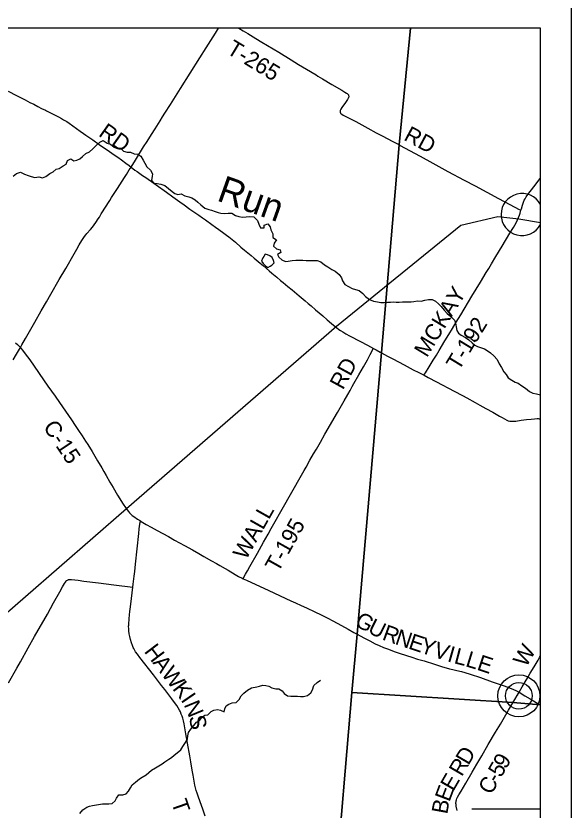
# Model space of a CAD drawing. Extents: x 0 to 34, y 0 to 22.
# Drawn here: x 7.205 to 9.17, y 17.655 to 20.469 of the extents above; entities that cross this region are included whole.
import ezdxf

# ---------------------------------------------------------------- set-up
doc = ezdxf.new("R2010")
doc.units = 0
for name, color, linetype in [('Default', 7, 'Continuous'), ('GM_X_County_Road', 7, 'Continuous'), ('GM_X_County_Road_Text', 7, 'Continuous'), ('GM_X_Interstate_Shield', 7, 'Continuous'), ('GM_X_Minor_Lake', 7, 'Continuous'), ('GM_X_Minor_River', 7, 'Continuous'), ('GM_X_Minor_River_Text', 7, 'Continuous'), ('GM_X_Rail_Line', 7, 'Continuous'), ('GM_X_State_Shield', 7, 'Continuous'), ('GM_X_Township_Road', 7, 'Continuous'), ('GM_X_Township_Road_Text', 7, 'Continuous'), ('GM_X_Unincorporated', 7, 'Continuous'), ('GM_X_Unincorporated_Location', 7, 'Continuous'), ('SH_Cut_Line', 7, 'Continuous'), ('SH_Data', 7, 'Continuous')]:
    doc.layers.add(name, color=color, linetype=linetype)

msp = doc.modelspace()

# ---------------------------------------------------------------- linework, layer by layer
at = {"layer": 'Default'}
msp.add_lwpolyline([(8.3334, 17.361), (8.3935, 18.0719), (8.4126, 18.2788), (8.4989, 19.2757), (8.562, 20.012), (8.6014, 20.4252), (3.5682, 20.4252), (3.5424, 20.1754), (3.5231, 19.8516), (3.5169, 19.7823), (3.5125, 19.7343), (3.5092, 19.6961), (3.5066, 19.6647), (3.4966, 19.5464), (3.4903, 19.4759), (3.4748, 19.2963), (3.47, 19.2407), (3.2768, 17.1355)], dxfattribs=at)
for points in [[(9.0621, 18.0279), (9.0621, 20.4252), (8.6014, 20.4252), (8.562, 20.012), (8.4989, 19.2757), (8.4126, 18.2788), (8.3935, 18.0719), (8.9638, 18.036), (9.0619, 18.0279)], [(8.4279, 13.6252), (9.0621, 13.6252), (9.0621, 18.0279), (9.0619, 18.0279), (8.9638, 18.036), (8.3935, 18.0719), (8.3334, 17.361), (8.3307, 17.3314), (8.3286, 17.3076), (8.2895, 16.85), (8.2031, 16.209), (8.146, 15.4642), (8.137, 15.3372), (8.1234, 15.1688), (8.3761, 15.1587), (8.4023, 15.1576), (8.4024, 15.1386)]]:
    msp.add_lwpolyline(points, close=True, dxfattribs=at)
at = {"layer": 'GM_X_County_Road'}
msp.add_line((8.964, 18.0355), (8.9861, 18.0728), dxfattribs=at)
for points in [[(7.6123, 19.933), (7.6276, 19.9574), (7.6569, 20.0042), (7.6695, 20.0242), (7.6847, 20.0484), (7.6975, 20.0689), (7.7151, 20.0967), (7.724, 20.1109), (7.7322, 20.124), (7.7514, 20.1546), (7.7874, 20.2112), (7.8562, 20.3199), (7.8784, 20.3551), (7.8953, 20.3819), (7.9114, 20.4077), (7.9221, 20.4252)], [(7.2208, 19.2936), (7.2261, 19.3034), (7.2389, 19.3261), (7.253, 19.351), (7.2716, 19.3833), (7.2945, 19.4238), (7.3129, 19.4563), (7.3284, 19.4832), (7.358, 19.5343), (7.381, 19.5741), (7.4104, 19.6252), (7.4198, 19.642), (7.4287, 19.6577), (7.4376, 19.6727), (7.4427, 19.6806), (7.4474, 19.6872), (7.4517, 19.6925), (7.4557, 19.6973), (7.4685, 19.7117), (7.476, 19.7207), (7.482, 19.7286), (7.488, 19.7372), (7.4958, 19.7492), (7.5, 19.7561), (7.5069, 19.7672), (7.5244, 19.795), (7.532, 19.8071), (7.537, 19.815), (7.5436, 19.8255), (7.5522, 19.8392), (7.5638, 19.8575), (7.5723, 19.8706), (7.5892, 19.8966), (7.5956, 19.9065), (7.6059, 19.9228), (7.6123, 19.933)], [(7.2034, 19.3104), (7.2104, 19.3042), (7.2162, 19.2985), (7.2208, 19.2936)], [(7.195, 19.2497), (7.2071, 19.2707), (7.2136, 19.282), (7.2175, 19.2883), (7.2198, 19.292), (7.2208, 19.2936)], [(7.2208, 19.2936), (7.2222, 19.2921), (7.2281, 19.2848), (7.2379, 19.272), (7.2539, 19.2498), (7.3179, 19.1573), (7.3431, 19.1218), (7.3587, 19.0994), (7.3697, 19.0836), (7.3913, 19.0525), (7.4015, 19.0376), (7.415, 19.0175), (7.4264, 19.0004), (7.4392, 18.9813), (7.4515, 18.9627), (7.4595, 18.95), (7.4747, 18.9251), (7.494, 18.8925), (7.5086, 18.8672), (7.5157, 18.8548), (7.5241, 18.8402), (7.5374, 18.8164), (7.5484, 18.7976), (7.5644, 18.771), (7.5843, 18.7395), (7.5928, 18.7266), (7.5982, 18.719), (7.6032, 18.7127), (7.6073, 18.7081), (7.6116, 18.7037), (7.6167, 18.6993), (7.6226, 18.6948), (7.6348, 18.6864), (7.6452, 18.6798)], [(7.6452, 18.6798), (7.6479, 18.6781), (7.666, 18.6671), (7.6833, 18.6573), (7.7044, 18.6456), (7.7444, 18.624), (7.7667, 18.6118), (7.8011, 18.593), (7.8294, 18.5774), (7.8528, 18.5645), (7.8705, 18.5542), (7.8975, 18.5388), (7.9147, 18.5288), (7.9271, 18.5217), (7.946, 18.5111), (7.9558, 18.5056), (7.9814, 18.4902), (7.9931, 18.4833), (8.0057, 18.4767), (8.0093, 18.4749)], [(8.0093, 18.4749), (8.0208, 18.4693), (8.0998, 18.4331), (8.1777, 18.3971), (8.194, 18.3895), (8.2148, 18.3797), (8.2335, 18.3713), (8.2629, 18.3579), (8.2859, 18.3468), (8.3086, 18.3352), (8.3266, 18.3255), (8.3572, 18.3088), (8.381, 18.2957)], [(8.381, 18.2957), (8.4013, 18.2845), (8.4128, 18.2783)], [(8.4128, 18.2783), (8.4368, 18.2653), (8.4572, 18.2548), (8.4772, 18.2447), (8.4906, 18.2383), (8.506, 18.2317), (8.5239, 18.2248), (8.5438, 18.2176), (8.5655, 18.2102), (8.6063, 18.1971), (8.627, 18.1905), (8.6496, 18.1836), (8.687, 18.1718), (8.7148, 18.163), (8.7279, 18.1593), (8.7399, 18.1562), (8.752, 18.1535), (8.7659, 18.1503), (8.7822, 18.146), (8.7947, 18.1423), (8.8125, 18.1368), (8.8497, 18.1244), (8.8915, 18.1102), (8.9331, 18.0958), (8.949, 18.0901), (8.9582, 18.0864), (8.9746, 18.0789), (8.9861, 18.0728)], [(8.9861, 18.0728), (9.0067, 18.0605), (9.0252, 18.0491), (9.0584, 18.0296), (9.0621, 18.0274)], [(8.7667, 17.6541), (8.7637, 17.6688), (8.7629, 17.6748), (8.7626, 17.6788), (8.7626, 17.682), (8.7629, 17.6851), (8.7636, 17.6883), (8.7643, 17.6913), (8.7661, 17.696), (8.7682, 17.7006), (8.7727, 17.7089), (8.7806, 17.7223), (8.7977, 17.7511), (8.8199, 17.7892), (8.8367, 17.8183), (8.8538, 17.8471), (8.877, 17.8876), (8.9033, 17.9319), (8.9201, 17.9602), (8.9488, 18.0097), (8.964, 18.0355)]]:
    msp.add_lwpolyline(points, dxfattribs=at)
at = {"layer": 'GM_X_Interstate_Shield'}
msp.add_line((8.8184, 17.6593), (9.0621, 17.6593), dxfattribs=at)
at = {"layer": 'GM_X_Minor_Lake'}
for points in [[(8.079, 19.6112), (8.0772, 19.6088), (8.074, 19.6001), (8.0802, 19.5912), (8.0888, 19.5827), (8.0971, 19.5776), (8.1051, 19.5816), (8.1105, 19.5861)], [(8.1105, 19.5861), (8.1186, 19.5939), (8.1169, 19.6027), (8.1122, 19.6126), (8.104, 19.6189), (8.096, 19.6221), (8.0877, 19.6241), (8.083, 19.6166), (8.079, 19.6112)]]:
    msp.add_lwpolyline(points, dxfattribs=at)
at = {"layer": 'GM_X_Minor_River'}
for points in [[(7.1953, 19.9005), (7.2073, 19.9106), (7.2214, 19.9145), (7.2345, 19.9081), (7.2485, 19.9029), (7.2587, 19.8993), (7.2715, 19.896), (7.2852, 19.8991), (7.2992, 19.8951), (7.3107, 19.8994), (7.3242, 19.9109), (7.3369, 19.9167), (7.3473, 19.9256), (7.358, 19.9284), (7.3718, 19.9369), (7.3822, 19.9428), (7.387, 19.9567), (7.3989, 19.9626), (7.4098, 19.9551), (7.4201, 19.958), (7.4304, 19.9623), (7.4401, 19.9709), (7.452, 19.9809), (7.4647, 19.9875), (7.4767, 19.9979), (7.4891, 20.0101), (7.5014, 20.0209), (7.5141, 20.0275), (7.5272, 20.0177), (7.5397, 20.0148), (7.5531, 20.0039), (7.5633, 19.9988), (7.5754, 19.9997), (7.5859, 19.99), (7.5987, 19.9859), (7.6108, 19.9857), (7.6233, 19.9801), (7.6361, 19.9787), (7.6474, 19.9713), (7.6555, 19.9574), (7.661, 19.9475), (7.6687, 19.9344), (7.6806, 19.9216), (7.6879, 19.9093), (7.6873, 19.8995), (7.6844, 19.8866), (7.6941, 19.8758), (7.7043, 19.8748), (7.7176, 19.8727), (7.7323, 19.8682), (7.745, 19.8577), (7.7577, 19.8464), (7.7678, 19.839), (7.778, 19.8357), (7.7898, 19.8385), (7.8033, 19.8311), (7.8173, 19.8277), (7.8275, 19.8245), (7.8391, 19.8167), (7.8488, 19.8089), (7.8596, 19.7992), (7.8734, 19.7879), (7.8874, 19.7831), (7.8976, 19.7802), (7.91, 19.7754), (7.9202, 19.7725), (7.93, 19.7704)], [(7.93, 19.7704), (7.9429, 19.7683), (7.9566, 19.7695), (7.9691, 19.7693), (7.9823, 19.7614), (7.9943, 19.7581), (8.0072, 19.756), (8.0201, 19.7572), (8.0331, 19.7581), (8.0475, 19.7563), (8.0597, 19.7439), (8.0648, 19.7305), (8.0706, 19.7183), (8.0835, 19.718), (8.0841, 19.7275), (8.0963, 19.7322), (8.1045, 19.721), (8.1077, 19.7111), (8.1142, 19.6961), (8.1147, 19.6832), (8.1275, 19.675), (8.1185, 19.663), (8.1168, 19.6532), (8.1276, 19.6438), (8.1405, 19.6405), (8.1425, 19.6306), (8.1314, 19.6236), (8.1354, 19.6141), (8.1466, 19.6047), (8.159, 19.5988), (8.1689, 19.6001), (8.1822, 19.6021), (8.1955, 19.603), (8.2088, 19.6039), (8.2206, 19.6032), (8.232, 19.6023), (8.2464, 19.6024), (8.2604, 19.6021), (8.2714, 19.6026), (8.2846, 19.5974), (8.297, 19.5873), (8.309, 19.5798), (8.3228, 19.5708), (8.3352, 19.5649), (8.3494, 19.5525), (8.3579, 19.5405), (8.3611, 19.5298), (8.3696, 19.5171), (8.382, 19.5097), (8.3951, 19.5029), (8.4076, 19.4997), (8.42, 19.4956), (8.4327, 19.4847), (8.442, 19.4743), (8.4566, 19.4637), (8.4706, 19.4585), (8.4846, 19.4556), (8.4963, 19.4535), (8.5088, 19.4536), (8.5198, 19.4545), (8.5309, 19.455), (8.5404, 19.4552), (8.5506, 19.455), (8.5612, 19.4548), (8.5734, 19.4553), (8.5829, 19.4552), (8.595, 19.4553), (8.6045, 19.4559), (8.614, 19.4568), (8.6262, 19.4592), (8.6395, 19.4586), (8.6525, 19.4617), (8.6651, 19.4645), (8.6787, 19.4639), (8.6908, 19.4576), (8.7012, 19.449), (8.7098, 19.4393), (8.7209, 19.4258), (8.732, 19.4146), (8.7451, 19.4041), (8.757, 19.3913), (8.7614, 19.3813), (8.7634, 19.3673), (8.7662, 19.3547), (8.7717, 19.3451), (8.7814, 19.338), (8.7964, 19.3298), (8.8088, 19.3215), (8.8196, 19.3107), (8.8293, 19.3025), (8.8391, 19.2978), (8.8534, 19.2929), (8.8636, 19.2893), (8.8733, 19.2834), (8.8853, 19.2752), (8.8972, 19.2643), (8.9084, 19.2512), (8.9153, 19.2363), (8.9234, 19.2228), (8.9322, 19.2082), (8.94, 19.1982)], [(8.8295, 19.3137), (8.8152, 19.3246), (8.8153, 19.3245)], [(8.94, 19.1982), (8.9481, 19.1866), (8.9601, 19.1777), (8.9729, 19.1713), (8.9827, 19.1677), (8.9961, 19.1587), (9.0092, 19.1497), (9.0227, 19.1384), (9.0347, 19.1325), (9.048, 19.1296), (9.0615, 19.1259), (9.0621, 19.1257)], [(7.8046, 17.8948), (7.8117, 17.9068), (7.8135, 17.9185), (7.8156, 17.9306), (7.8234, 17.9419), (7.8347, 17.9553), (7.8437, 17.9665), (7.8548, 17.9728), (7.8633, 17.9832), (7.8741, 17.991), (7.884, 17.9927), (7.8957, 18.0046), (7.9056, 18.009), (7.9186, 18.0121), (7.9288, 18.0096), (7.9416, 18.0033), (7.9441, 18.0143), (7.9488, 18.0241), (7.9584, 18.0303), (7.9707, 18.0354), (7.984, 18.0359), (7.9948, 18.0467), (8.0019, 18.0598), (8.0116, 18.0695), (8.0247, 18.0803), (8.0386, 18.088), (8.0576, 18.0914), (8.0672, 18.0946), (8.0794, 18.0974), (8.09, 18.0972), (8.1006, 18.0939), (8.1107, 18.088), (8.1255, 18.0851), (8.1353, 18.0853), (8.147, 18.0782), (8.1543, 18.0678), (8.166, 18.06), (8.1785, 18.0586), (8.1887, 18.0584), (8.2016, 18.0585), (8.2126, 18.0575), (8.2232, 18.0577), (8.237, 18.0608), (8.2493, 18.0709), (8.2548, 18.0818), (8.2593, 18.0961), (8.2709, 18.1069), (8.2832, 18.1161)], [(7.431, 17.6436), (7.4419, 17.6563), (7.4553, 17.6652), (7.4653, 17.6695), (7.4763, 17.6712), (7.4973, 17.675), (7.511, 17.6773), (7.5247, 17.6775), (7.5342, 17.6773), (7.5452, 17.6782), (7.5556, 17.6879), (7.5611, 17.6976), (7.5686, 17.7092), (7.583, 17.7089), (7.5948, 17.7125), (7.6038, 17.7222), (7.6109, 17.7346), (7.6168, 17.7447), (7.6283, 17.754), (7.6418, 17.7655), (7.6515, 17.7721), (7.6653, 17.7802), (7.6753, 17.788), (7.685, 17.7962), (7.6992, 17.805), (7.7111, 17.812), (7.7226, 17.8193), (7.7323, 17.826), (7.7457, 17.8352), (7.7554, 17.8415), (7.765, 17.8496), (7.7754, 17.8578), (7.7882, 17.8685), (7.7952, 17.8805), (7.8046, 17.8948)]]:
    msp.add_lwpolyline(points, dxfattribs=at)
at = {"layer": 'GM_X_Rail_Line'}
msp.add_lwpolyline([(9.0621, 19.736), (8.9849, 19.7484), (8.9112, 19.7568), (8.7798, 19.7259), (8.3393, 19.3678), (7.5966, 18.7228), (6.6419, 17.8912), (5.6319, 17.0784)], dxfattribs=at)
at = {"layer": 'GM_X_State_Shield'}
msp.add_line((9.0621, 19.7293), (9.0621, 19.8008), dxfattribs=at)
msp.add_arc((8.9969, 19.765), 0.0744, 28.7249, 331.2751, dxfattribs=at)
at = {"layer": 'GM_X_Township_Road'}
for points in [[(7.9936, 20.4252), (8.0093, 20.4153), (8.0254, 20.4058), (8.0537, 20.3888), (8.0754, 20.3756), (8.135, 20.3398), (8.1791, 20.3126), (8.2057, 20.2969), (8.2338, 20.2798), (8.2673, 20.2595), (8.2742, 20.2553), (8.2901, 20.2456), (8.3235, 20.2254), (8.3586, 20.205), (8.3693, 20.1987), (8.3753, 20.1949), (8.3771, 20.1936), (8.3801, 20.1914), (8.3811, 20.1904), (8.3818, 20.1892), (8.3825, 20.1876), (8.3828, 20.1861), (8.3832, 20.1844), (8.3832, 20.1829), (8.3832, 20.1813), (8.3827, 20.1797), (8.3812, 20.1766), (8.3786, 20.1722), (8.3715, 20.1619), (8.359, 20.1441), (8.3555, 20.1384), (8.3542, 20.1362), (8.3531, 20.1338), (8.3526, 20.1324), (8.3523, 20.1308), (8.3522, 20.129), (8.3525, 20.1272), (8.3529, 20.126), (8.3534, 20.1249), (8.3543, 20.1236), (8.3554, 20.1226), (8.3583, 20.1205), (8.3636, 20.1175), (8.3828, 20.1079), (8.408, 20.0945), (8.4509, 20.0706), (8.4805, 20.0547), (8.5019, 20.0434), (8.5392, 20.0236), (8.5623, 20.0114), (8.5631, 20.011)], [(7.1768, 20.202), (7.2066, 20.1866), (7.237, 20.1709), (7.2541, 20.1622), (7.2675, 20.1555), (7.2818, 20.1482), (7.2957, 20.1411), (7.3089, 20.1343), (7.3133, 20.1321), (7.3275, 20.125), (7.3385, 20.1195), (7.3557, 20.1109), (7.3656, 20.1057), (7.3736, 20.101), (7.3846, 20.094), (7.3928, 20.0885), (7.4317, 20.0608), (7.4439, 20.0523), (7.4526, 20.0463), (7.4633, 20.0389), (7.4766, 20.0297), (7.4994, 20.0136), (7.5153, 20.0027), (7.5316, 19.9913), (7.549, 19.9793), (7.5652, 19.968), (7.5788, 19.9582), (7.5942, 19.9466), (7.6051, 19.9385), (7.6123, 19.933)], [(8.5631, 20.011), (8.6361, 19.9715), (8.6803, 19.9474), (8.7343, 19.918), (8.7922, 19.8866), (8.8306, 19.8661), (8.8716, 19.8439), (8.9138, 19.8215), (8.9539, 19.8003), (8.9864, 19.7832), (8.9927, 19.7799)], [(7.6123, 19.933), (7.6259, 19.9227), (7.6334, 19.9171), (7.6528, 19.9036), (7.6646, 19.8956), (7.7374, 19.8437), (7.7607, 19.8271), (7.7848, 19.8097), (7.8, 19.7988), (7.821, 19.7844), (7.8347, 19.7747), (7.8524, 19.7622), (7.8652, 19.7534), (7.8758, 19.7458), (7.8985, 19.7295), (7.9111, 19.7204), (7.9227, 19.7121), (7.9408, 19.699), (7.9503, 19.6921), (7.9587, 19.6857), (7.9698, 19.6767), (7.9817, 19.6668), (8.0016, 19.6499), (8.0142, 19.6389), (8.0261, 19.6289), (8.0373, 19.6193), (8.0477, 19.6105), (8.0691, 19.5926), (8.0811, 19.5827), (8.1014, 19.5654), (8.1104, 19.5578), (8.1228, 19.5474), (8.1281, 19.543), (8.142, 19.5316), (8.1464, 19.5281), (8.1507, 19.5246), (8.1677, 19.5101), (8.1825, 19.4977), (8.2072, 19.477), (8.2287, 19.4591), (8.2392, 19.4503), (8.2496, 19.4415), (8.2657, 19.4278), (8.2779, 19.4173), (8.2911, 19.406), (8.3072, 19.3922), (8.3226, 19.3788), (8.3297, 19.3727), (8.3393, 19.3648), (8.3482, 19.358), (8.3538, 19.354), (8.3618, 19.3491), (8.3731, 19.3426), (8.3863, 19.3355), (8.4242, 19.3156), (8.45, 19.302), (8.4703, 19.2909)], [(8.9927, 19.7799), (8.9943, 19.7853), (8.998, 19.7981), (9.0016, 19.8086), (9.0047, 19.8159), (9.0073, 19.8208), (9.0112, 19.8271), (9.0176, 19.8362), (9.0383, 19.8634), (9.0604, 19.8926), (9.0621, 19.8949)], [(8.6496, 19.1957), (8.6518, 19.1992), (8.6552, 19.2046), (8.6682, 19.2259), (8.6824, 19.2492), (8.6934, 19.2673), (8.703, 19.2832), (8.7237, 19.3179), (8.7369, 19.3397), (8.7501, 19.3615), (8.7635, 19.3838), (8.7794, 19.4098), (8.8188, 19.4753), (8.8494, 19.5258), (8.87, 19.5598), (8.8787, 19.5741), (8.8887, 19.5906), (8.9041, 19.6161), (8.9268, 19.6532), (8.954, 19.6985), (8.9662, 19.7187), (8.9761, 19.736), (8.9812, 19.746), (8.9846, 19.754), (8.9877, 19.7629), (8.9899, 19.7704), (8.9927, 19.7799)], [(8.0093, 18.4749), (8.0108, 18.4778), (8.0177, 18.4908), (8.0241, 18.5029), (8.0328, 18.5187), (8.0595, 18.5657), (8.0813, 18.6041), (8.0979, 18.6332), (8.1089, 18.6527), (8.118, 18.669), (8.1468, 18.7212), (8.1811, 18.781), (8.1952, 18.8059), (8.2014, 18.8166), (8.2061, 18.8247), (8.2157, 18.8413), (8.2255, 18.8586), (8.232, 18.8699), (8.2457, 18.895), (8.2587, 18.9175), (8.2684, 18.9343), (8.2825, 18.9591), (8.2985, 18.9872), (8.343, 19.0641), (8.3669, 19.1056), (8.3794, 19.1271), (8.388, 19.1422), (8.3955, 19.1558), (8.4016, 19.1666), (8.4187, 19.1969), (8.435, 19.226), (8.4491, 19.2503), (8.4593, 19.2688), (8.4692, 19.2888), (8.4703, 19.2909)], [(8.4703, 19.2909), (8.4806, 19.2853), (8.4948, 19.2776), (8.4992, 19.2752)], [(8.4992, 19.2752), (8.51, 19.2692), (8.5203, 19.2635), (8.5274, 19.2597), (8.5391, 19.2538), (8.5798, 19.2325), (8.6116, 19.2154), (8.6308, 19.2052), (8.648, 19.1966), (8.6496, 19.1957)], [(8.6496, 19.1957), (8.6639, 19.1882), (8.6942, 19.1724), (8.7563, 19.1396), (8.7853, 19.124), (8.8017, 19.1153), (8.8305, 19.0994), (8.8472, 19.0899), (8.8679, 19.0783), (8.8935, 19.0644), (8.9168, 19.0513), (8.9258, 19.0459), (8.9428, 19.0367), (8.948, 19.0343), (8.953, 19.0331), (8.9561, 19.0327), (8.9612, 19.0325), (8.9674, 19.0327), (8.9749, 19.0335), (8.9934, 19.0362), (9.0124, 19.0387), (9.0285, 19.0405), (9.0408, 19.0418), (9.05, 19.0424), (9.0537, 19.0422), (9.0579, 19.0418), (9.0621, 19.0409)], [(7.6188, 18.4454), (7.6203, 18.4561), (7.6235, 18.4845), (7.6252, 18.5006), (7.6279, 18.5259), (7.6396, 18.6353), (7.6415, 18.6519), (7.6437, 18.6686), (7.6452, 18.6798)], [(7.1782, 18.1065), (7.2076, 18.1584), (7.2204, 18.1804), (7.2485, 18.2302), (7.2707, 18.2697), (7.316, 18.349), (7.338, 18.3892), (7.36, 18.4281), (7.3699, 18.446), (7.3765, 18.458), (7.3798, 18.4629), (7.3822, 18.466), (7.3843, 18.4681), (7.3867, 18.47), (7.3894, 18.4713), (7.3911, 18.4719), (7.3941, 18.4724), (7.3971, 18.4726), (7.4014, 18.4724), (7.4248, 18.4693), (7.4457, 18.4665), (7.4975, 18.4601), (7.5512, 18.4535), (7.6188, 18.4454)], [(7.8748, 17.6338), (7.8663, 17.6584), (7.8616, 17.672), (7.8515, 17.7007), (7.8465, 17.7147), (7.8434, 17.7248), (7.8408, 17.7343), (7.8387, 17.7434), (7.836, 17.758), (7.8325, 17.7788), (7.8292, 17.7972), (7.8239, 17.8259), (7.8199, 17.8479), (7.8121, 17.892), (7.8063, 17.925), (7.7999, 17.9605), (7.7976, 17.9715), (7.7952, 17.9806), (7.793, 17.9877), (7.7902, 17.9953), (7.787, 18.0028), (7.7836, 18.0095), (7.7793, 18.0172), (7.774, 18.0256), (7.7662, 18.0369), (7.7569, 18.0493), (7.7316, 18.0824), (7.7205, 18.0966), (7.6912, 18.1345), (7.6437, 18.1959), (7.635, 18.2072), (7.6285, 18.2163), (7.6246, 18.2226), (7.6219, 18.2274), (7.6198, 18.2318), (7.6171, 18.2387), (7.614, 18.2481), (7.6107, 18.2594), (7.6078, 18.2708), (7.6062, 18.28), (7.6047, 18.2904), (7.6041, 18.2971), (7.6038, 18.3064), (7.6039, 18.3103), (7.6041, 18.3144), (7.6056, 18.3323), (7.6069, 18.3471), (7.608, 18.3588), (7.6099, 18.3754), (7.6134, 18.405), (7.6188, 18.4454)], [(8.9861, 18.0728), (8.9972, 18.0919), (9.0074, 18.1096), (9.0171, 18.1255), (9.0256, 18.14), (9.0338, 18.1539), (9.043, 18.1687), (9.0532, 18.186), (9.0587, 18.1954), (9.0621, 18.2012)]]:
    msp.add_lwpolyline(points, dxfattribs=at)
at = {"layer": 'GM_X_Unincorporated'}
for radius in [0.0744, 0.0472]:
    msp.add_circle((8.9856, 18.06), radius, dxfattribs=at)
at = {"layer": 'GM_X_Unincorporated_Location'}
for p, q in [((8.9969, 19.765), (8.9969, 19.765)), ((8.9856, 18.06), (8.9856, 18.06))]:
    msp.add_line(p, q, dxfattribs=at)
at = {"layer": 'SH_Cut_Line'}
msp.add_lwpolyline([(2.9696, 13.6252), (9.0621, 13.6252), (9.0621, 20.4252), (3.5682, 20.4252), (3.5424, 20.1754), (3.5231, 19.8516), (3.5169, 19.7823), (3.5125, 19.7343), (3.5092, 19.6961), (3.5066, 19.6647), (3.4966, 19.5464), (3.4903, 19.4759), (3.4748, 19.2963), (3.47, 19.2407), (3.2768, 17.1355), (3.2667, 16.919), (3.1974, 16.1596), (3.1343, 15.4291), (3.0617, 14.6751), (3.0457, 14.4958), (3.0429, 14.4692)], close=True, dxfattribs=at)
at = {"layer": 'SH_Data'}
msp.add_line((9.1704, 20.5628), (9.1704, 13.5628), dxfattribs=at)

# ---------------------------------------------------------------- texts
at = {"layer": 'GM_X_County_Road_Text'}
for s, height, rotation, p in [('C-15', 0.05682, 303.6894, (7.2992, 19.0128)), ('G', 0.0568, 330.9718, (8.4009, 18.3111)), ('U', 0.0568, 333.453, (8.447, 18.2856)), ('R', 0.0568, 340.2225, (8.4985, 18.2604)), ('N', 0.0568, 341.5914, (8.5438, 18.2441)), ('E', 0.0568, 341.6005, (8.5913, 18.2283)), ('Y', 0.0568, 341.6068, (8.6316, 18.2149)), ('V', 0.0568, 342.1055, (8.6796, 18.1989)), ('I', 0.0568, 343.9915, (8.7291, 18.183)), ('L', 0.0568, 345.4927, (8.7531, 18.1761)), ('L', 0.0568, 342.8059, (8.7936, 18.1656)), ('E', 0.0568, 341.7805, (8.8339, 18.1532)), ('D', 0.0568, 59.6949, (8.807, 17.8116)), ('R', 0.0568, 59.6919, (8.7834, 17.7714)), ('9', 0.0568, 59.7323, (8.9396, 17.798)), ('5', 0.0568, 59.7788, (8.922, 17.7678)), ('E', 0.0568, 59.9811, (8.7533, 17.7195)), ('C', 0.0568, 61.7801, (8.8885, 17.7069)), ('-', 0.0568, 59.9279, (8.9103, 17.7476)), ('E', 0.0568, 69.2152, (8.7393, 17.682)), ('B', 0.0568, 79.66, (8.7317, 17.6387))]:
    msp.add_text(s, height=height, rotation=rotation, dxfattribs=at).set_placement(p)
at = {"layer": 'GM_X_Minor_River_Text'}
msp.add_text('Run', height=0.0947, rotation=340.3485, dxfattribs=at).set_placement((7.9124, 19.8157))
at = {"layer": 'GM_X_Township_Road_Text'}
for s, height, rotation, p in [('T-265', 0.05682, 328.8482, (7.9471, 20.3381)), ('RD', 0.05682, 324.8059, (7.4942, 20.0458)), ('RD', 0.05682, 331.8923, (8.5745, 20.0306)), ('MCKAY', 0.05682, 58.7254, (8.6598, 19.256)), ('T-192', 0.05682, 58.7039, (8.7731, 19.2089)), ('RD', 0.05682, 61.2338, (8.3624, 19.1413)), ('WALL', 0.05682, 60.5762, (8.0193, 18.5385)), ('T-195', 0.05682, 60.6738, (8.1332, 18.4944)), ('H', 0.0568, 307.2371, (7.6566, 18.2171)), ('W', 0.0568, 59.1476, (9.0106, 18.1584)), ('A', 0.0568, 307.2357, (7.6868, 18.1773)), ('W', 0.0568, 307.2329, (7.7171, 18.1375)), ('K', 0.0568, 307.1264, (7.7569, 18.0851)), ('I', 0.0568, 304.4338, (7.7866, 18.0458)), ('N', 0.0568, 292.4562, (7.7983, 18.0293)), ('S', 0.0568, 281.5601, (7.8166, 17.9858)), ('T', 0.0568, 289.2197, (7.754, 17.6826))]:
    msp.add_text(s, height=height, rotation=rotation, dxfattribs=at).set_placement(p)

doc.saveas('drawing.dxf')
